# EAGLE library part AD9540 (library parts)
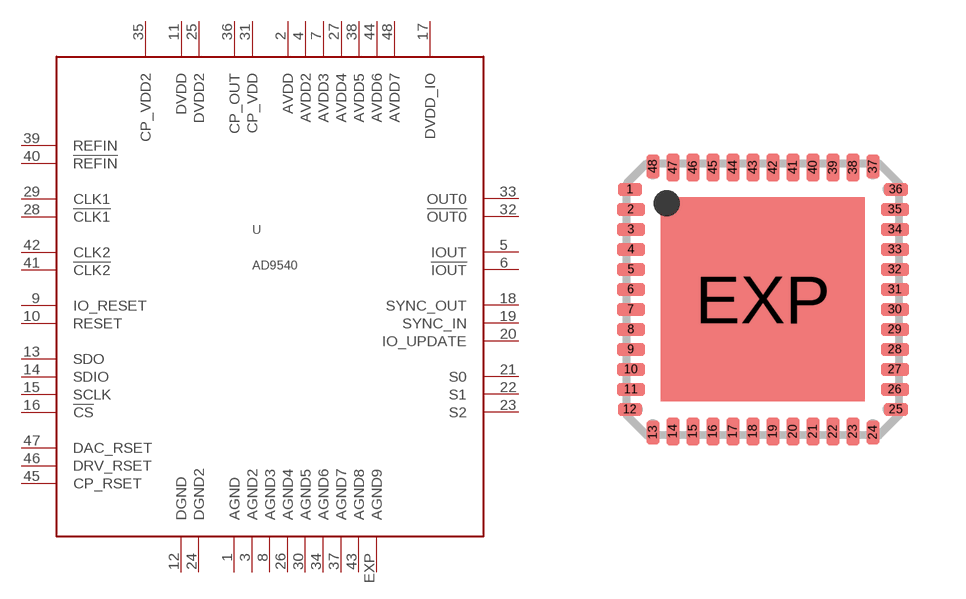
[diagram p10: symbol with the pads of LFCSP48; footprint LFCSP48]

Designator prefix -

## AD9540  [LFCSP48]
1  AGND
2  AVDD
3  AGND2
4  AVDD2
5  IOUT
6  !IOUT
7  AVDD3
8  AGND3
9  IO_RESET
10  RESET
11  DVDD
12  DGND
13  SDO
14  SDIO
15  SCLK
16  !CS
17  DVDD_IO
18  SYNC_OUT
19  SYNC_IN
20  IO_UPDATE
21  S0
22  S1
23  S2
24  DGND2
25  DVDD2
26  AGND4
27  AVDD4
28  !CLK1
29  CLK1
30  AGND5
31  CP_VDD
32  !OUT0
33  OUT0
34  AGND6
35  CP_VDD2
36  CP_OUT
37  AGND7
38  AVDD5
39  REFIN
40  !REFIN
41  !CLK2
42  CLK2
43  AGND8
44  AVDD6
45  CP_RSET
46  DRV_RSET
47  DAC_RSET
48  AVDD7
EXP  AGND9

## Footprint LFCSP48 (pad centres in mm)
Lead Frame Chip Scale Package LFCSP CP-48 COMPLIANT TO JEDEC STANDARDS MO-220-VKKD-2 Source: http://www.analog.com/UploadedFiles/Data_Sheets/39780344872292AD7651_0.pdf
smd 0.6 x 0.32: 1 -3.325,2.75; 12 -3.325,-2.75; 25 3.325,-2.75; 36 3.325,2.75
smd 0.7 x 0.32: 2 -3.3,2.25; 3 -3.3,1.75; 4 -3.3,1.25; 5 -3.3,0.75; 6 -3.3,0.25; 7 -3.3,-0.25; 8 -3.3,-0.75; 9 -3.3,-1.25; 10 -3.3,-1.75; 11 -3.3,-2.25; 26 3.3,-2.25; 27 3.3,-1.75; 28 3.3,-1.25; 29 3.3,-0.75; 30 3.3,-0.25; 31 3.3,0.25; 32 3.3,0.75; 33 3.3,1.25; 34 3.3,1.75; 35 3.3,2.25
smd 0.32 x 0.6: 13 -2.75,-3.325; 24 2.75,-3.325; 37 2.75,3.325; 48 -2.75,3.325
smd 0.32 x 0.7: 14 -2.25,-3.3; 15 -1.75,-3.3; 16 -1.25,-3.3; 17 -0.75,-3.3; 18 -0.25,-3.3; 19 0.25,-3.3; 20 0.75,-3.3; 21 1.25,-3.3; 22 1.75,-3.3; 23 2.25,-3.3; 38 2.25,3.3; 39 1.75,3.3; 40 1.25,3.3; 41 0.75,3.3; 42 0.25,3.3; 43 -0.25,3.3; 44 -0.75,3.3; 45 -1.25,3.3; 46 -1.75,3.3; 47 -2.25,3.3
smd 5.1 x 5.1: EXP 0,0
